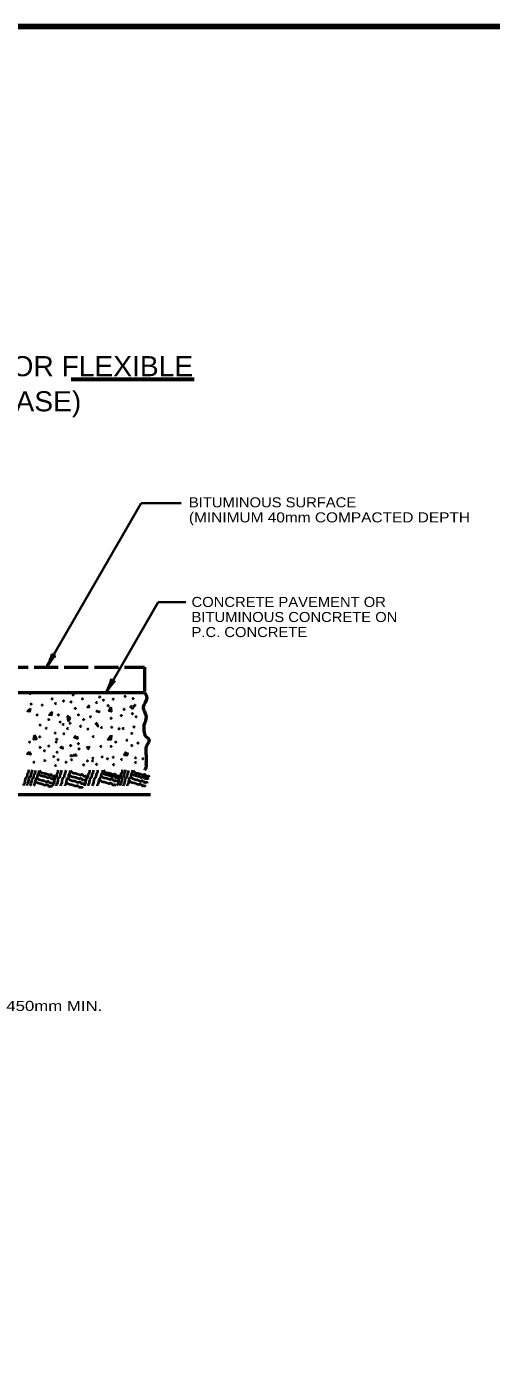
# Model space of a CAD drawing. Extents: x -617 to 238, y 23 to 567.
# Drawn here: x -163.5 to -52.3, y 243.8 to 560.4 of the extents above; entities that cross this region are included whole.
import ezdxf
from ezdxf.enums import TextEntityAlignment as Align

# ---------------------------------------------------------------- set-up
doc = ezdxf.new("R2010")
doc.units = 0
doc.header["$LTSCALE"] = 0.96
doc.linetypes.add('LONG_DASHED', pattern=[7.5, 6, -1.5])
doc.layers.add('1', color=7, linetype='Continuous', lineweight=40)

msp = doc.modelspace()

# ---------------------------------------------------------------- linework, layer by layer
at = {"layer": '1', "lineweight": 60}
msp.add_line((-152.8416, 476.0042), (-123.3943, 476.0042), dxfattribs=at)
at = {"layer": '1', "lineweight": 35}
for p, q in [((-158.7282, 407.1379), (-136.0821, 446.362)), ((-136.0821, 446.362), (-126.4821, 446.362)), ((-144.4998, 401.1379), (-132.0331, 422.7308)), ((-132.0331, 422.7308), (-125.4331, 422.7308))]:
    msp.add_line(p, q, dxfattribs=at)
at = {"layer": '1', "linetype": 'LONG_DASHED', "lineweight": 53}
for p, q in [((-327.291, 407.1379), (-135.291, 407.1379)), ((-135.291, 407.1379), (-135.291, 401.1379))]:
    msp.add_line(p, q, dxfattribs=at)
at = {"layer": '1', "lineweight": 53}
for p, q in [((-327.291, 401.1379), (-135.291, 401.1379)), ((-325.834, 376.7054), (-133.834, 376.7054))]:
    msp.add_line(p, q, dxfattribs=at)
at = {"layer": '1', "lineweight": 158}
msp.add_lwpolyline([(231.8054, 560.3585), (-559.8946, 560.2585), (-559.7946, 34.2585)], dxfattribs=at)
at = {"layer": '1', "lineweight": 35}
for points in [[(-162.8515, 397.0892), (-163.2948, 396.646), (-162.7038, 396.5721), (-162.5561, 397.3847)], [(-157.6067, 396.3505), (-158.1238, 395.7595), (-157.5329, 395.6857), (-157.3851, 396.5721)], [(-148.4468, 398.1234), (-148.9639, 397.6063), (-148.5207, 397.6063), (-148.6685, 398.1234)], [(-143.3498, 397.6802), (-143.793, 396.7198), (-143.2021, 396.5721), (-143.2759, 397.5324)], [(-138.3266, 397.9756), (-138.696, 397.6802), (-138.1789, 397.2369), (-137.8834, 397.6802), (-138.105, 397.9756)], [(-153.6916, 395.3902), (-153.5439, 394.2821), (-153.1007, 395.0947), (-153.7655, 395.6118)], [(-147.1172, 393.765), (-146.3785, 392.9525), (-146.6001, 393.6173), (-146.9694, 393.9128)], [(-161.6696, 390.8102), (-161.8174, 389.8499), (-161.0787, 389.9977), (-161.5958, 390.958)], [(-151.6971, 390.8102), (-152.1404, 390.367), (-151.2539, 390.0715), (-151.4017, 390.6625)], [(-143.3498, 390.8102), (-144.0885, 389.8499), (-143.2759, 389.8499), (-143.2021, 390.8841)], [(-162.8515, 386.8951), (-163.3686, 386.4519), (-162.4822, 386.3041), (-162.8515, 386.969)], [(-155.0213, 388.2986), (-155.3907, 387.9293), (-154.7997, 387.7077), (-154.9474, 388.2248)], [(-152.0026, 386.3936), (-152.4459, 385.9504), (-151.5594, 386.0243), (-151.8549, 386.4675)], [(-149.1117, 388.2248), (-148.7423, 387.5599), (-148.4468, 388.077), (-149.1117, 388.1509)], [(-139.6563, 386.8951), (-140.1734, 386.1564), (-139.4347, 386.0825), (-139.2869, 386.7474)]]:
    msp.add_lwpolyline(points, dxfattribs=at)
for centre in [(-162.6299, 400.8566), (-157.3851, 399.6008), (-154.6519, 399.0837), (-152.8791, 398.8621), (-152.362, 400.5611), (-150.1459, 399.6008), (-146.0091, 400.044), (-145.1227, 399.3053), (-142.7588, 399.5269), (-139.9518, 400.1917), (-138.0311, 399.6747), (-162.4083, 398.345), (-161.0048, 395.7595), (-159.749, 398.1234), (-156.5726, 398.4927), (-155.9077, 395.7595), (-151.8449, 397.3108), (-151.1062, 395.7595), (-146.7478, 398.7143), (-146.674, 396.646), (-146.1569, 396.4982), (-144.0146, 397.9756), (-140.8382, 395.6118), (-140.1734, 397.0892), (-138.1789, 396.055), (-137.5879, 398.0495), (-160.2661, 393.3218), (-158.7887, 392.5831), (-158.1977, 394.6515), (-155.4645, 394.0605), (-154.7258, 393.4696), (-153.6916, 392.5092), (-153.1007, 393.765), (-150.5891, 393.0263), (-149.8504, 394.6515), (-148.2252, 395.3163), (-145.5659, 392.7309), (-143.2759, 394.947), (-143.1282, 392.8047), (-141.3553, 392.4354), (-140.395, 392.5092), (-137.8095, 392.8786), (-137.2924, 395.3163), (-162.7777, 389.2589), (-160.34, 390.5147), (-156.6464, 391.4012), (-156.4248, 389.2589), (-156.2771, 389.9238), (-154.5781, 391.2534), (-148.8162, 392.3615), (-147.5604, 390.5886), (-142.1679, 389.2589), (-139.5085, 389.7022), (-138.3266, 391.3273), (-160.2661, 388.0032), (-159.2319, 387.1906), (-158.1977, 388.2986), (-156.2032, 386.8212), (-152.9529, 388.4464), (-151.1062, 388.8896), (-150.9584, 387.6338), (-145.7136, 388.2248), (-143.2759, 388.2248), (-138.3266, 388.4464), (-136.8492, 389.0373), (-161.7435, 384.4574), (-159.158, 384.8267), (-157.0158, 385.787), (-156.5726, 383.6448), (-155.9816, 385.0483), (-154.061, 384.4574), (-152.8791, 386.0087), (-152.7313, 385.0483), (-149.8504, 383.7926), (-148.9639, 384.7529), (-147.7081, 384.7529), (-147.6343, 385.4177), (-146.7478, 383.9403), (-145.4182, 385.7132), (-144.1624, 385.27), (-142.7588, 385.6393), (-142.685, 383.8664), (-140.7643, 385.1222), (-137.4402, 385.4916), (-137.4402, 384.3835), (-135.6673, 385.27)]:
    msp.add_circle(centre, 0.12, dxfattribs=at)
at = {"layer": '1'}
for centre, major_axis, ratio, start_param, end_param in [((-158.3606, 408.4377), (-0.9091, -1.9494), 0.122415, 0.89635335, 3.14159265), ((-158.3606, 408.4377), (-0.9091, -1.9494), 0.122415, 0.89635335, 3.14159265), ((-157.836, 408.1754), (-1.2364, -1.72), 0.07063, 3.14071475, 5.41810995), ((-157.836, 408.1754), (-1.2364, -1.72), 0.07063, 3.14071475, 5.41810995), ((-144.1322, 402.4377), (-0.9091, -1.9494), 0.122415, 0.89635335, 3.14159265), ((-143.6076, 402.1754), (1.2364, 1.72), 0.07063, 6.28230741, 8.55970261)]:
    msp.add_ellipse(centre, major_axis=major_axis, ratio=ratio, start_param=start_param, end_param=end_param, dxfattribs=at)
at = {"layer": '1', "lineweight": 53}
msp.add_spline([(-135.291, 401.1379), (-134.7554, 399.8612), (-135.5975, 397.6357), (-135.2967, 396.553), (-134.9358, 394.8087), (-135.417, 393.305), (-135.3569, 391.5607), (-135.1764, 390.899), (-134.214, 389.8164), (-134.7554, 388.4329), (-134.9358, 387.7713), (-134.9358, 386.3879), (-134.8757, 385.1849), (-134.9358, 384.1624), (-134.9358, 383.2601), (-135.291, 382.5379)], degree=3, dxfattribs=at)
at = {"layer": '1'}
for points in [[(-163.0111, 382.5948), (-163.1137, 382.0129), (-163.3361, 381.6021), (-163.4644, 380.8745), (-163.8325, 380.4894), (-163.858, 380.344), (-163.935, 379.9074), (-164.0119, 379.4709), (-164.2345, 379.0602), (-164.2602, 378.9146)], [(-162.1985, 382.5948), (-162.3011, 382.0129), (-162.5235, 381.6021), (-162.6518, 380.8745), (-163.0199, 380.4894), (-163.0454, 380.344), (-163.1224, 379.9074), (-163.1993, 379.4709), (-163.4219, 379.0602), (-163.4476, 378.9146)], [(-161.4598, 382.447), (-161.5624, 381.8651), (-161.7848, 381.4543), (-161.9131, 380.7267), (-162.2812, 380.3416), (-162.3067, 380.1962), (-162.3837, 379.7596), (-162.4606, 379.3231), (-162.6832, 378.9124), (-162.7089, 378.7668)], [(-160.5734, 382.447), (-160.676, 381.8651), (-160.8984, 381.4543), (-161.0267, 380.7267), (-161.3948, 380.3416), (-161.4203, 380.1962), (-161.4973, 379.7596), (-161.5742, 379.3231), (-161.7968, 378.9124), (-161.8225, 378.7668)], [(-161.3514, 380.0021), (-160.9999, 379.6018), (-160.0009, 379.3342), (-159.7155, 379.2578), (-158.8593, 379.0283), (-158.6783, 379.1328), (-158.1838, 378.6945), (-157.5749, 378.6841), (-157.4704, 378.5033)], [(-161.0559, 380.8147), (-160.7044, 380.4144), (-159.7054, 380.1468), (-159.42, 380.0704), (-158.5638, 379.8409), (-158.3828, 379.9454), (-157.8883, 379.5071), (-157.2794, 379.4967), (-157.1749, 379.3159)], [(-160.6865, 381.775), (-160.335, 381.3747), (-159.336, 381.1071), (-159.0506, 381.0307), (-158.1944, 380.8012), (-158.0134, 380.9057), (-157.5189, 380.4674), (-156.91, 380.457), (-156.8055, 380.2762)], [(-160.391, 382.4399), (-160.0395, 382.0396), (-159.0405, 381.772), (-158.7551, 381.6956), (-157.8989, 381.4661), (-157.7179, 381.5706), (-157.2234, 381.1323), (-156.6145, 381.1219), (-156.51, 380.9411)], [(-155.9934, 382.5209), (-156.096, 381.939), (-156.3184, 381.5282), (-156.4467, 380.8006), (-156.8148, 380.4155), (-156.8403, 380.2701), (-156.9173, 379.8335), (-156.9942, 379.397), (-157.2168, 378.9863), (-157.2425, 378.8407)], [(-155.1808, 382.5209), (-155.2834, 381.939), (-155.5058, 381.5282), (-155.6341, 380.8006), (-156.0022, 380.4155), (-156.0277, 380.2701), (-156.1047, 379.8335), (-156.1816, 379.397), (-156.4042, 378.9863), (-156.4299, 378.8407)], [(-154.1466, 382.5209), (-154.2492, 381.939), (-154.4716, 381.5282), (-154.5999, 380.8006), (-154.968, 380.4155), (-154.9935, 380.2701), (-155.0705, 379.8335), (-155.1474, 379.397), (-155.37, 378.9863), (-155.3957, 378.8407)], [(-153.1124, 382.447), (-153.215, 381.8651), (-153.4374, 381.4543), (-153.5657, 380.7267), (-153.9338, 380.3416), (-153.9593, 380.1962), (-154.0363, 379.7596), (-154.1132, 379.3231), (-154.3358, 378.9124), (-154.3615, 378.7668)], [(-153.5211, 380.667), (-153.1696, 380.2667), (-152.1706, 379.9991), (-151.8852, 379.9227), (-151.029, 379.6932), (-150.848, 379.7977), (-150.3535, 379.3594), (-149.7446, 379.349), (-149.6401, 379.1682)], [(-153.2995, 381.5534), (-152.948, 381.1531), (-151.949, 380.8855), (-151.6636, 380.8091), (-150.8074, 380.5796), (-150.6264, 380.6841), (-150.1319, 380.2458), (-149.523, 380.2354), (-149.4185, 380.0546)], [(-153.004, 382.4399), (-152.6525, 382.0396), (-151.6535, 381.772), (-151.3681, 381.6956), (-150.5119, 381.4661), (-150.3309, 381.5706), (-149.8364, 381.1323), (-149.2275, 381.1219), (-149.123, 380.9411)], [(-148.4586, 382.5209), (-148.5612, 381.939), (-148.7836, 381.5282), (-148.9119, 380.8006), (-149.28, 380.4155), (-149.3055, 380.2701), (-149.3825, 379.8335), (-149.4594, 379.397), (-149.682, 378.9863), (-149.7077, 378.8407)], [(-147.5721, 382.5209), (-147.6747, 381.939), (-147.8971, 381.5282), (-148.0254, 380.8006), (-148.3935, 380.4155), (-148.419, 380.2701), (-148.496, 379.8335), (-148.5729, 379.397), (-148.7955, 378.9863), (-148.8212, 378.8407)], [(-146.5379, 382.5209), (-146.6405, 381.939), (-146.8629, 381.5282), (-146.9912, 380.8006), (-147.3593, 380.4155), (-147.3848, 380.2701), (-147.4618, 379.8335), (-147.5387, 379.397), (-147.7613, 378.9863), (-147.787, 378.8407)], [(-145.356, 382.5209), (-145.4586, 381.939), (-145.681, 381.5282), (-145.8093, 380.8006), (-146.1774, 380.4155), (-146.2029, 380.2701), (-146.2799, 379.8335), (-146.3568, 379.397), (-146.5794, 378.9863), (-146.6051, 378.8407)], [(-146.0602, 380.3715), (-145.7087, 379.9712), (-144.7097, 379.7036), (-144.4243, 379.6272), (-143.5681, 379.3977), (-143.3871, 379.5022), (-142.8926, 379.0639), (-142.2837, 379.0535), (-142.1792, 378.8727)], [(-145.7647, 381.3318), (-145.4132, 380.9315), (-144.4142, 380.6639), (-144.1288, 380.5875), (-143.2726, 380.358), (-143.0916, 380.4625), (-142.5971, 380.0242), (-141.9882, 380.0138), (-141.8837, 379.833)], [(-145.3954, 382.0705), (-145.0439, 381.6702), (-144.0449, 381.4026), (-143.7595, 381.3262), (-142.9033, 381.0967), (-142.7223, 381.2012), (-142.2278, 380.7629), (-141.6189, 380.7525), (-141.5144, 380.5717)], [(-145.0999, 382.5138), (-144.7484, 382.1135), (-143.7494, 381.8459), (-143.464, 381.7695), (-142.6078, 381.54), (-142.4268, 381.6445), (-141.9323, 381.2062), (-141.3234, 381.1958), (-141.2189, 381.015)], [(-140.6284, 382.5948), (-140.731, 382.0129), (-140.9534, 381.6021), (-141.0817, 380.8745), (-141.4498, 380.4894), (-141.4753, 380.344), (-141.5523, 379.9074), (-141.6292, 379.4709), (-141.8518, 379.0602), (-141.8775, 378.9146)], [(-139.8897, 382.5948), (-139.9923, 382.0129), (-140.2147, 381.6021), (-140.343, 380.8745), (-140.7111, 380.4894), (-140.7366, 380.344), (-140.8136, 379.9074), (-140.8905, 379.4709), (-141.1131, 379.0602), (-141.1388, 378.9146)], [(-139.151, 382.447), (-139.2536, 381.8651), (-139.476, 381.4543), (-139.6043, 380.7267), (-139.9724, 380.3416), (-139.9979, 380.1962), (-140.0749, 379.7596), (-140.1518, 379.3231), (-140.3744, 378.9124), (-140.4001, 378.7668)], [(-138.1907, 382.5209), (-138.2933, 381.939), (-138.5157, 381.5282), (-138.644, 380.8006), (-139.0121, 380.4155), (-139.0376, 380.2701), (-139.1146, 379.8335), (-139.1915, 379.397), (-139.4141, 378.9863), (-139.4398, 378.8407)], [(-138.9686, 380.1499), (-138.6171, 379.7496), (-137.6181, 379.482), (-137.3327, 379.4056), (-136.4765, 379.1761), (-136.2955, 379.2806), (-135.801, 378.8423), (-135.1921, 378.8319), (-135.0876, 378.6511)], [(-138.5254, 380.9625), (-138.1739, 380.5622), (-137.1749, 380.2946), (-136.8895, 380.2182), (-136.0333, 379.9887), (-135.8523, 380.0932), (-135.3578, 379.6549), (-134.7489, 379.6445), (-134.6444, 379.4637)], [(-138.3038, 381.8489), (-137.9523, 381.4486), (-136.9533, 381.181), (-136.6679, 381.1046), (-135.8117, 380.8751), (-135.6307, 380.9796), (-135.1362, 380.5413), (-134.5273, 380.5309), (-134.4228, 380.3501)], [(-138.0083, 382.4399), (-137.6568, 382.0396), (-136.6578, 381.772), (-136.3724, 381.6956), (-135.5162, 381.4661), (-135.3352, 381.5706), (-134.8407, 381.1323), (-134.2318, 381.1219), (-134.1273, 380.9411)], [(-154.0382, 379.7805), (-153.6867, 379.3802), (-152.6877, 379.1126), (-152.4023, 379.0362), (-151.5461, 378.8067), (-151.3651, 378.9112), (-150.8706, 378.4729), (-150.2617, 378.4625), (-150.1572, 378.2817)]]:
    msp.add_spline(points, degree=3, dxfattribs=at)

# ---------------------------------------------------------------- texts
for s, height, width, p in [('MINIMUM REPLACEMENT REQUIREMENT FOR RIGID OR FLEXIBLE', 4.8, 1.05, (-231.8799, 476.7396)), ('PAVEMENT CUTS (INCLUDING BASE & SUB-BASE)', 4.8, 1.05, (-231.8799, 468.3396)), ('450mm MIN.', 2.4, 1.25, (-156.8722, 324.9872))]:
    msp.add_text(s, height=height, dxfattribs=dict(at, width=width)).set_placement(p, align=Align.CENTER)
for s, width, p in [('BITUMINOUS SURFACE', 1.1, (-124.6674, 445.39)), ('(MINIMUM 40mm COMPACTED DEPTH', 1.15, (-124.6674, 441.79)), ('CONCRETE PAVEMENT OR', 1.1, (-124.0343, 421.5687)), ('BITUMINOUS CONCRETE ON', 1.1, (-124.0343, 417.9687)), ('P.C. CONCRETE', 1.1, (-124.0343, 414.3687))]:
    msp.add_text(s, height=2.4, dxfattribs=dict(at, width=width)).set_placement(p)

doc.saveas('drawing.dxf')
